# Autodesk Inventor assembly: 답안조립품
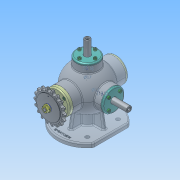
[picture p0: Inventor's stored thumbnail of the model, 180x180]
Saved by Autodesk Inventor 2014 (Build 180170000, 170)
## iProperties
Created: 2016-03
Part Number: 답안조립품
Document SubType Name: Assembly
Designer: net
Author: net
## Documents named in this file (17)
- C:\Users\net\Desktop\360307V1002\답안조립품.iam
- C:\Users\net\Desktop\360307V1002\본체.ipt
- C:\Users\net\Desktop\360307V1002\축.ipt
- C:\Users\net\Desktop\360307V1002\키 3 x 3 x 12.ipt
- C:\Users\net\Desktop\360307V1002\베어링- 6202.ipt
- C:\Users\net\Desktop\360307V1002\앞커버.ipt
- C:\Users\net\Desktop\360307V1002\오일실.ipt
- C:\Users\net\Desktop\360307V1002\볼트 M4x0.7.ipt
- C:\Users\net\Desktop\360307V1002\스프로킷.ipt
- C:\Users\net\Desktop\360307V1002\와셔 8x17.ipt
- C:\Users\net\Desktop\360307V1002\너트-M8x1.ipt
- C:\Users\net\Desktop\360307V1002\뒤커버.ipt
- C:\Users\net\Desktop\360307V1002\슬라이드.ipt
- C:\Users\net\Desktop\360307V1002\슬라이드 커버.ipt
- C:\Users\net\Desktop\360307V1002\본체커버.ipt
- C:\Users\net\Desktop\360307V1002\스프링2.ipt
- C:\Users\net\Desktop\360307V1002\스프링1.ipt
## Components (17 placed, 1 different names)
1. M4x0.7x12:17
2. M4x0.7x12:1
3. M4x0.7x12:3
4. M4x0.7x12:4
5. M4x0.7x12:5
6. M4x0.7x12:2
7. M4x0.7x12:6
8. M4x0.7x12:7
9. M4x0.7x12:8
10. M4x0.7x12:10
11. M4x0.7x12:11
12. M4x0.7x12:12
13. M4x0.7x12:13
14. M4x0.7x12:9
15. M4x0.7x12:14
16. M4x0.7x12:15
17. M4x0.7x12:16
